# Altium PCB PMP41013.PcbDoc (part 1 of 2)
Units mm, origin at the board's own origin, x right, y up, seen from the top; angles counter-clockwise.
Board outline 51.82 x 50.04 mm, 2 copper layers (Top Layer, Bottom Layer), stack 0.325 mm thick; 134 components, 74 nets, 429 pads, 1513 vias.
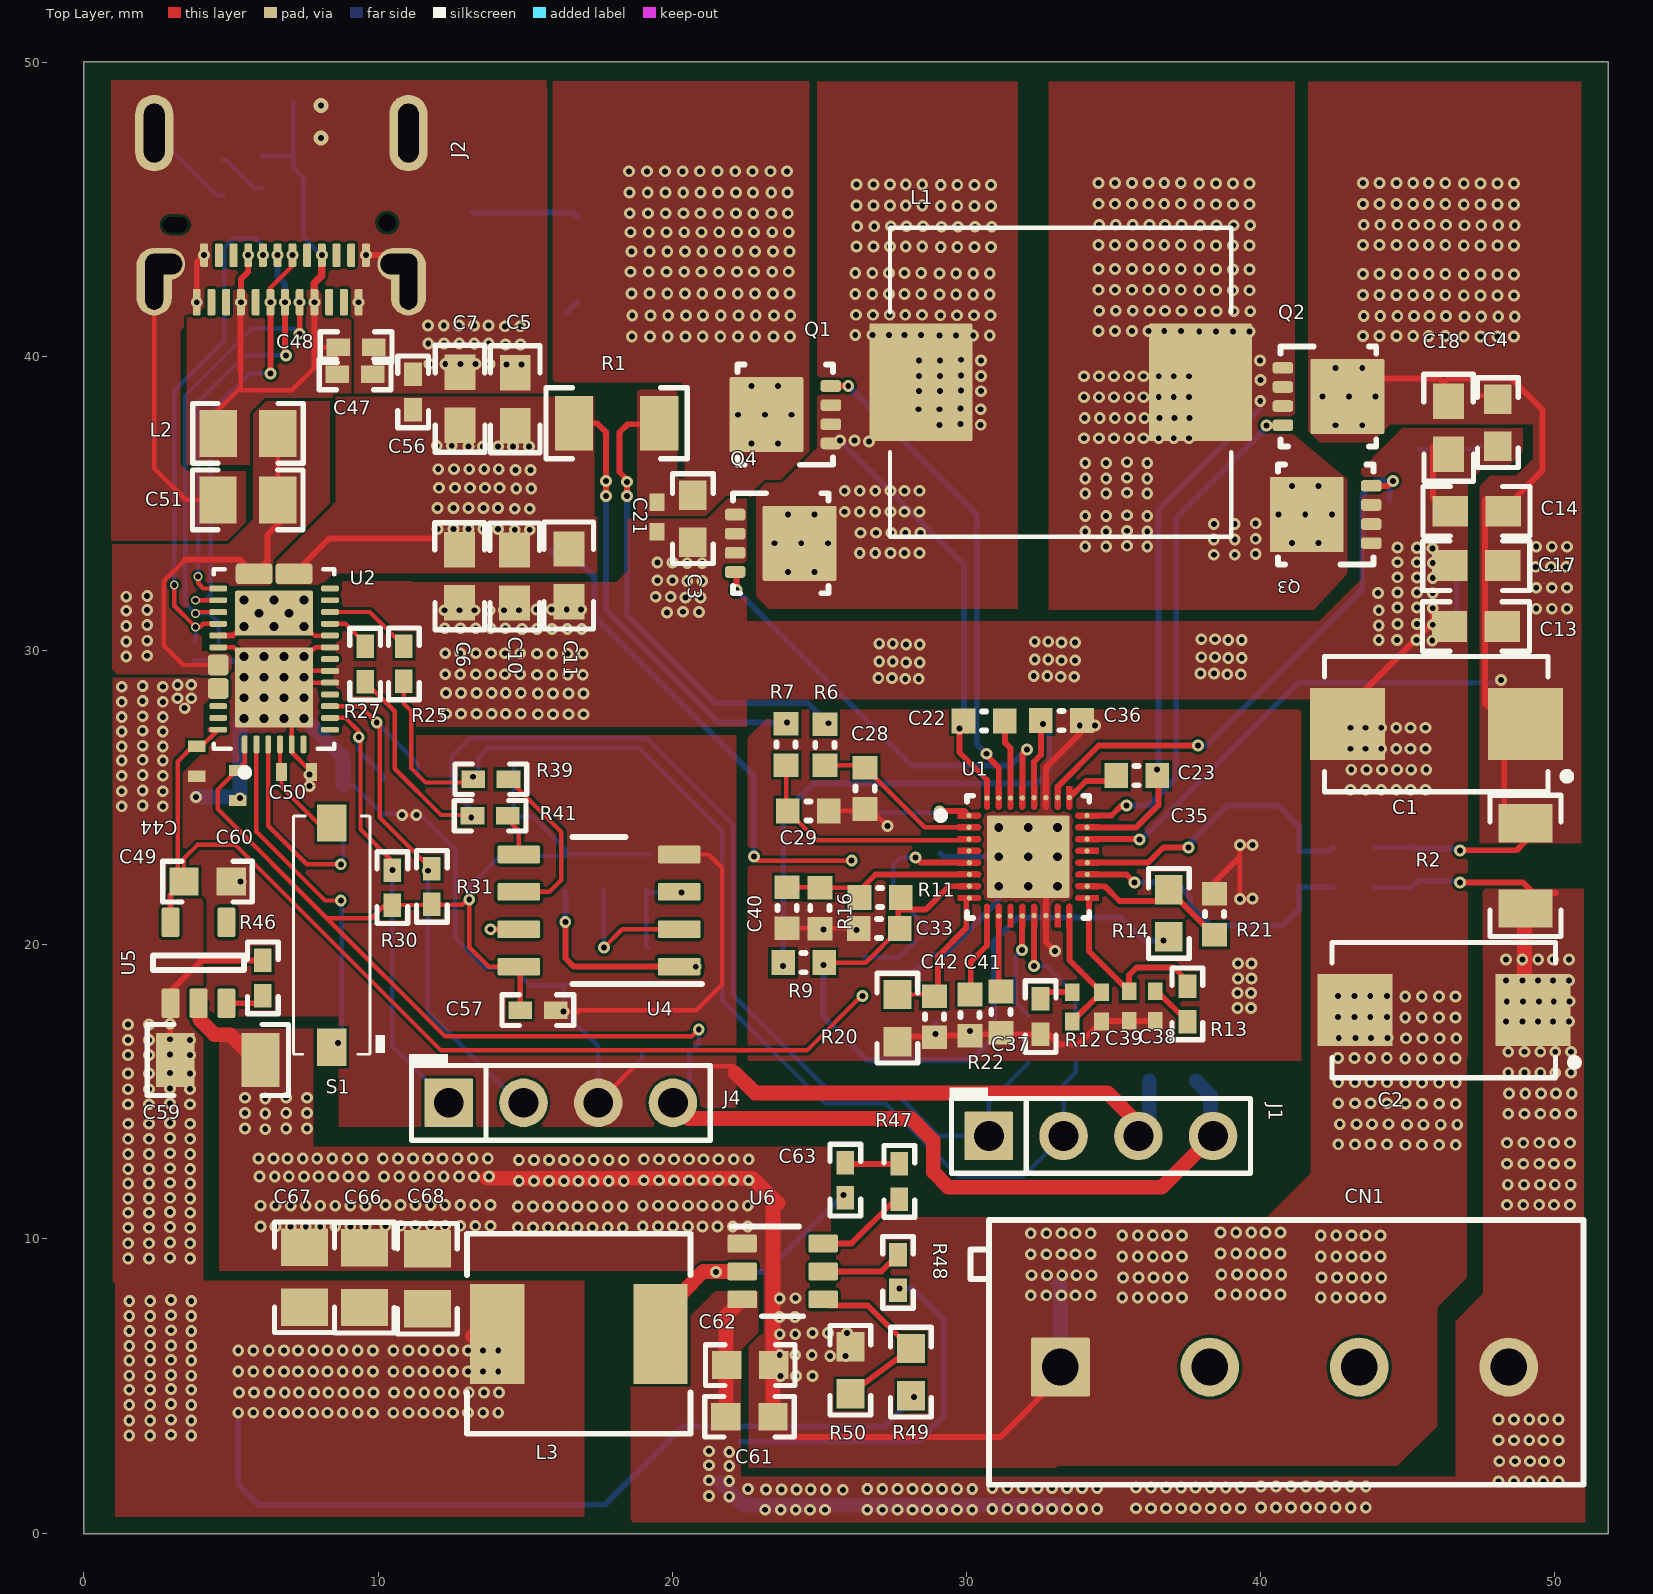
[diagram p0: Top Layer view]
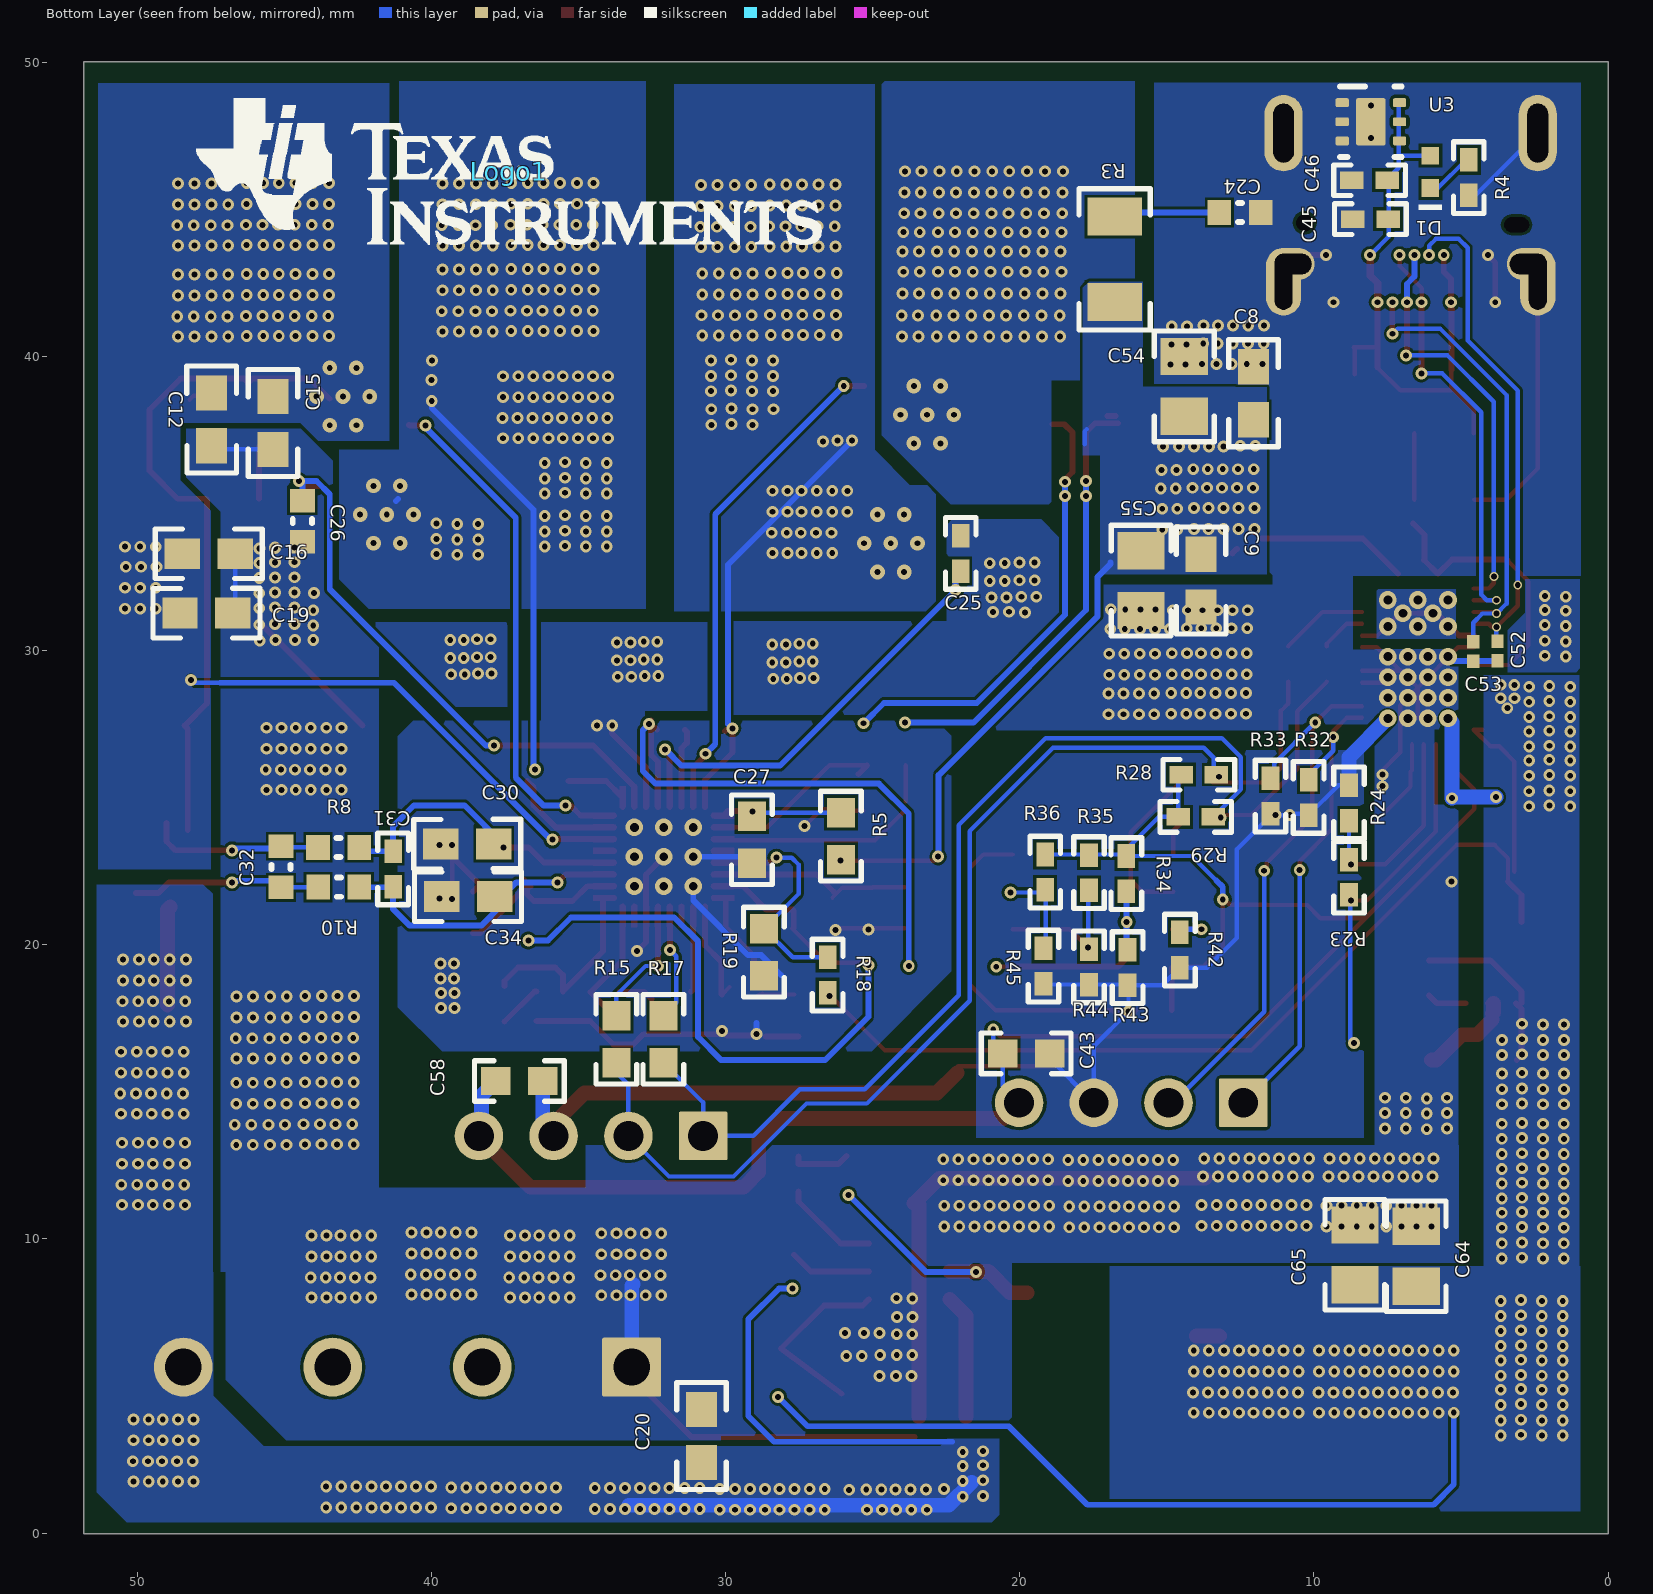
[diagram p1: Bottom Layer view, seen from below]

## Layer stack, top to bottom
Top Solder: solder mask 0.0102, Solder Resist, Dk 3.5
Top Layer: signal copper 0.0356
Dielectric 1: core 0.254, FR-4, Dk 4.2
Bottom Layer: signal copper 0.0356
Bottom Solder: solder mask 0.0102, Solder Resist, Dk 3.5

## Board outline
51.816,50.013 51.816,-0.025 0,-0.025 0,50.013

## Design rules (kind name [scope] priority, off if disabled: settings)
Clearance Clearance_1 [All] p1: gap=0.1 ignorepadtopadclearanceinfootprint=FALSE
ComponentClearance [All] p1: gap=0.05 collisioncheckmode=3 verticalgap=0.05 showdistances=FALSE
DiffPairsRouting [All] p1: maxlimit=0.254 minlimit=0.2 mostfreqgap=0.2 toplayer_minwidth=0.15 toplayer_maxwidth=0.381 toplayer_prefwidth=0.2 bottomlayer_minwidth=0.15 bottomlayer_maxwidth=0.381 bottomlayer_prefwidth=0.2 maxuncoupledlength=12.7
HoleSize [All] p1: absolutevalues=TRUE maxlimit=2.54 minlimit=0.1 maxpercent=80.000 minpercent=20.000
HoleToHoleClearance [All] p1: gap=0.1 allowstackedmicrovias=TRUE
MinimumSolderMaskSliver [All] p1: minsoldermaskwidth=0
NetAntennae [All] p1: netantennaetolerance=0.2
PlaneConnect [All] p1: planeconnectstyle=Direct reliefexpansion=0.508 reliefentries=4 reliefconductorwidth=0.254 reliefairgap=0.254
PolygonConnect [All] p1: connectstyle=Direct reliefconductorwidth=0.254 reliefentries=4 polygonreliefangle="90 Angle" airgapwidth=0.254
RoutingVias [All] p1: holewidth=0.3 width=0.5 viastyle="Through Hole" minholewidth=0.1 minwidth=0.2 maxholewidth=1 maxwidth=1.3
SMDToCorner [All] p1: distance=78740
SilkToSilkClearance [All] p1: silktosilkclearance=0
SilkToSolderMaskClearance [IsPad] p1: minsilkscreentomaskgap=0 clearancetoexposedcopper=TRUE
SolderMaskExpansion [All] p1: expansion=0.102
UnConnectedPin [All] p1:
UnRoutedNet [All] p1: checkbadconnections=TRUE
Width [All] p1: maxlimit=2 minlimit=0.15 preferedwidth=0.2
20 further rules are at their usual default settings.

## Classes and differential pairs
component class PMP41013_Hardware: !PCB Logo1
component class Logo: Logo1
component class Header: J1 J4
component class "TPS25750 USB PD Control": C44 C45 C46 C47 C48 C49 C50 C51 C52 C53 C54 C55 C56 C57 C58 C59 C60 C61 C62 C63 C64 C65 C66 C67 C68 D1 J2 J4 L2 L3 R4 R23 R24 R25 R27 R28 R29 R30 R31 R32 R33 R34 R35 R36 R39 R41 R42 R43 R44 R45 R46 R47 R48 R49 R50 S1 U2 U3 U4 U5 U6
component class "BQ25731 Charger": C1 C2 C3 C4 C5 C6 C7 C8 C9 C10 C11 C12 C13 C14 C15 C16 C17 C18 C19 C20 C21 C22 C23 C24 C25 C26 C27 C28 C29 C30 C31 C32 C33 C34 C35 C36 C37 C38 C39 C40 C41 C42 C43 CN1 J1 L1 Q1 Q2 Q3 Q4 R1 R2 R3 R5 R6 R7 R8 R9 R10 R11 R12 R13 R14 R15 R16 R17 R18 R19 R20 R21 R22 U1
differential pair CSO: +CSO_P -CSO_N

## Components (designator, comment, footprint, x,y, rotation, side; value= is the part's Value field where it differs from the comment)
C1 "Capacitor" 7343-31 45.972,27.5 r180 top value=33uF
C2 "Capacitor" 7343-31 46.229,17.777 r180 top value=33uF
C3 "T521D336M035ATE065" 0603 20.699,34.486 r270 top value=0.01uF
C4 "T521D336M035ATE065" 0603 48.062,37.75 r270 top value=0.01uF
C5 "Capacitor" 0603M 14.666,38.544 r90 top value=10uF
C6 "Capacitor" 0603M 12.775,32.525 r270 top value=10uF
C7 "Capacitor" 0603M 12.79,38.557 r90 top value=10uF
C8 "Capacitor" 0603M 12.057,38.743 r90 bottom value=10uF
C9 "Capacitor" 0603M 13.838,32.378 r270 bottom value=10uF
C10 "Capacitor" 0603M 14.645,32.52 r270 top value=10uF
C11 "Capacitor" 0603M 16.486,32.555 r270 top value=10uF
C12 "Capacitor" 0603M 47.471,37.857 r270 bottom value=10uF
C13 "Capacitor" 0603M 47.319,30.818 r180 top value=10uF
C14 "Capacitor" 0603M 47.344,34.734 r180 top value=10uF
C15 "Capacitor" 0603M 45.386,37.736 r270 bottom value=10uF
C16 "Capacitor" 0603M 47.573,33.291 r180 bottom value=10uF
C17 "Capacitor" 0603M 47.331,32.885 r180 top value=10uF
C18 "Capacitor" 0603M 46.392,37.571 r270 top value=10uF
C19 "Capacitor" 0603M 47.649,31.271 r180 bottom value=10uF
C20 "Capacitor" 0603M 30.82,3.302 r90 bottom value=10uF
C21 "Capacitor" 0402L 19.48,34.544 r270 top value=1000pF
C22 "Capacitor" 0603L 30.603,27.606 r180 top value=0.047uF
C23 "Capacitor" 0603L 35.788,25.745 r0 top value=0.047uF
C24 "Capacitor" 0603L 12.515,44.891 r180 bottom value=1uF
C25 "885012005062" 0402 22.01,33.302 r270 bottom value=150pF
C26 "Capacitor" 0603L 44.388,34.4 r90 bottom value=150pF
C27 "C1608X5R1H474K080AB" 0603 29.107,23.57 r270 bottom value=0.47uF
C28 "Capacitor" 0603L 26.56,25.315 r90 top value=0.033uF
C29 "Capacitor" 0603L 24.627,24.549 r0 top value=0.033uF
C30 "GRM188R71H183KA01D" 0603M 38.785,23.421 r0 bottom value=0.018uF
C31 "GRM155R61A683KA01D" 0402 41.302,22.579 r270 bottom value=0.068uF
C32 "Capacitor" 0603L 45.112,22.648 r270 bottom value=0.1uF
C33 "Capacitor" 0603L 27.036,20.549 r180 top value=1uF
C34 "GRM188R71H183KA01D" 0603M 38.752,21.634 r0 bottom value=0.018uF
C35 "Capacitor" 0402L 34.593,17.889 r90 top value=33pF
C36 "Capacitor" 0603L 33.23,27.616 r0 top value=2.2uF
C37 "885012205029" 0402 32.522,17.559 r270 top value=4700pF
C38 "Capacitor" 0402L 36.422,17.914 r270 top value=680pF
C39 "Capacitor" 0402L 35.533,17.914 r270 top value=15pF
C40 "Capacitor" 0603L 23.911,21.257 r270 top value=100pF
C41 "Capacitor" 0603L 30.123,17.609 r270 top value=100pF
C42 "Capacitor" 0603L 28.912,17.552 r270 top value=100pF
C43 "0603YC104JAT2A" 0603 19.786,16.307 r0 bottom value=0.1uF
C44 "CL05A106MP5NUNC" 0402_070 3.839,26.237 r270 top value=10uF
C45 "C0402C103J5RACTU" 0402 8.082,44.665 r0 bottom value=0.01uF
C46 "C0402C103J5RACTU" 0402 8.112,45.988 r0 bottom value=0.01uF
C47 "C0402C103J5RACTU" 0402 9.22,39.388 r0 top value=0.01uF
C48 "C0402C103J5RACTU" 0402 9.253,40.313 r0 top value=0.01uF
C49 "CL05A106MP5NUNC" 0402_070 5.232,25.413 r90 top value=10uF
C50 "CL05A106MP5NUNC" 0402_070 7.227,25.875 r180 top value=10uF
C51 "C2012X7R1V475M125AC" 0805_HV 5.575,35.122 r180 top value=4.7uF
C52 "CGA1A2X7R1H221K030BA" 0201_033 3.762,29.981 r270 bottom value=220pF
C53 "CGA1A2X7R1H221K030BA" 0201_033 4.588,29.971 r270 bottom value=220pF
C54 "C2012X5R1V226M125AC" 0805_HV 14.41,38.981 r90 bottom value=22uF
C55 "C2012X5R1V226M125AC" 0805_HV 15.873,32.378 r270 bottom value=22uF
C56 "GMK105BJ104KV-F" 0402 11.192,38.791 r90 top value=0.1uF
C57 "GMK105BJ104KV-F" 0402 15.435,17.776 r0 top value=0.1uF
C58 "0603YC104JAT2A" 0603 37.012,15.37 r0 bottom value=0.1uF
C59 "GRM31MR71H105KA88L" 1206 4.557,16.081 r0 top value=1uF
C60 "CGA3E3X5R1A225K080AB" 0603 4.205,22.144 r0 top value=2.2uF
C61 "C3225X5R1H106K250AB" 0603 22.627,3.956 r0 top value=10uF
C62 "C1608X5R1H224K080AB" 0603 22.652,5.709 r0 top value=0.22uF
C63 "GRM155R61H104ME14D" 0402 25.887,11.996 r270 top value=0.1uF
C64 "GRM219R61C226ME15L" 0805_HV 6.525,9.409 r90 bottom value=22uF
C65 "GRM219R61C226ME15L" 0805_HV 8.608,9.46 r90 bottom value=22uF
C66 "GRM219R61C226ME15L" 0805_HV 9.534,8.684 r90 top value=22uF
C67 "GRM219R61C226ME15L" 0805_HV 7.502,8.698 r90 top value=22uF
C68 "GRM219R61C226ME15L" 0805_HV 11.678,8.647 r90 top value=22uF
CN1 "ED120/4DS" On-Shore_ED120_4DS 40.814,5.643 r0 top
D1 "LW QH8G-Q2S2-3K5L-1" "LW QH8G_White" 6.046,46.271 r270 bottom value=White
J1 "TSW-104-07-G-S" TSW-104-07-G-S 34.575,13.502 r0 top
J2 "DX07S024JJ2R1300" JAE_DX07S024JJ2R1300 6.714,49.39 r180 top
J4 "TSW-104-07-G-S" TSW-104-07-G-S 16.215,14.629 r0 top
L1 "BMQADY1010404R7MA1" FP-BMQADY1010404R7MA1_SMD2-MFG 33.203,39.119 r0 top
L2 "FBMJ2125HM210NT" 0805_HV 5.581,37.38 r0 top value="21 ohm"
L3 "SRP6540-5R6M" SRP6540 16.827,6.777 r180 top value=5.6uH
Logo1 "Texas Instruments" TI_Stacked_Overlay_Small 37.363,46.279 r180 bottom
Q1 "CSD17577Q3A" DNH0008A 23.846,38.017 r180 top value=30V
Q2 "CSD17577Q3A" DNH0008A 42.307,38.636 r0 top value=30V
Q3 "CSD17577Q3A" DNH0008A 42.214,34.625 r180 top value=30V
Q4 "CSD17577Q3A" DNH0008A 23.688,33.647 r0 top value=30V
R1 "Resistor" 1206 18.111,37.727 r0 top value=0.01
R2 "Resistor" 1206 49.006,22.683 r270 top value=0.01
R3 "CRCW12063R90JNEA" 1206 16.776,43.301 r270 bottom value=3.9
R4 "CRCW040210K0JNED" 0402 4.738,46.076 r90 bottom value=10k
R5 "RC0603FR-071RL" 0603 26.079,23.693 r90 bottom value=1.00
R6 "Resistor" 0603L 25.187,26.796 r90 top value=4.99
R7 "Resistor" 0603L 23.872,26.806 r90 top value=4.99
R8 "Resistor" 0603L 43.156,23.309 r180 bottom value=10
R9 "Resistor" 0603L 24.47,19.39 r0 top value=10.0
R10 "Resistor" 0603L 43.148,21.956 r180 bottom value=10
R11 "Resistor" 0603L 27.067,21.604 r180 top value=383k
R12 "Resistor" 0402L 33.603,17.889 r270 top value=40.2k
R13 "CRCW040215K0FKED" 0402 37.514,17.99 r270 top value=15.0k
R14 "CRCW06031K00FKEA" 0603 36.879,21.067 r270 top value=1.00k
R15 "RMCF0603ZT0R00" 0603 33.712,16.788 r90 bottom value=0
R16 "RC0603FR-07220KL" 0603L 25.018,21.243 r270 top value=220k
R17 "RMCF0603ZT0R00" 0603 32.112,16.788 r90 bottom value=0
R18 "CRCW04021K00FKED" 0402 26.531,18.971 r90 bottom value=1.00k
R19 "CRCW060310K0FKEA" 0603 28.699,19.749 r90 bottom value=10.0k
R20 "CRCW0603191KFKEA" 0603 27.657,17.508 r90 top value=191k
R21 "RC0603FR-07120KL" 0603L 38.432,21.04 r270 top value=120k
R22 "Resistor" 0603L 31.171,17.711 r270 top value=30.1k
R23 "RC0402JR-070RL" 0402 8.81,22.294 r270 bottom value=0
R24 "RMCF0402FT100K" 0402 8.812,24.823 r270 bottom value=100k
R25 "RC0402JR-070RL" 0402 10.881,29.549 r270 top value=0
R27 "RC0402JR-070RL" 0402 9.561,29.543 r270 top value=0
R28 "CRCW04022K20FKED" 0402 13.915,25.781 r180 bottom value=2.20k
R29 "CRCW04022K20FKED" 0402 14.019,24.349 r180 bottom value=2.20k
R30 "CRCW04022K20FKED" 0402 10.488,21.939 r270 top value=2.20k
R31 "CRCW04022K20FKED" 0402 11.831,21.985 r270 top value=2.20k
R32 "RC0402JR-070RL" 0402 10.183,25.009 r90 bottom value=0
R33 "RC0402JR-070RL" 0402 11.48,25.052 r90 bottom value=0
R34 "CRCW040210K0JNED" 0402 16.378,22.416 r90 bottom value=10k
R35 "CRCW040210K0JNED" 0402 17.647,22.449 r90 bottom value=10k
R36 "CRCW040210K0JNED" 0402 19.137,22.468 r90 bottom value=10k
R39 "RC0402JR-070RL" 0402 13.836,25.626 r0 top value=0
R41 "RC0402JR-070RL" 0402 13.813,24.383 r0 top value=0
R42 "CRCW040210K0JNED" 0402 14.56,19.818 r90 bottom value=10k
R43 "CRCW040210K0JNED" 0402 16.338,19.222 r90 bottom value=10k
R44 "CRCW040210K0JNED" 0402 17.647,19.248 r90 bottom value=10k
R45 "CRCW040210K0JNED" 0402 19.193,19.274 r90 bottom value=10k
R46 "RC0402JR-070RL" 0402 6.086,18.871 r90 top value=0
R47 "CRCW040230R0JNED" 0402 27.723,11.954 r90 top value=30
R48 "RC0402JR-070RL" 0402 27.677,8.864 r270 top value=0
R49 "CRCW060352K3FKEA" 0603 28.115,5.475 r270 top value=52.3k
R50 "CRCW060310K0FKEA" 0603 26.056,5.538 r270 top value=10.0k
S1 "CHS-01TB" SW_CHS-01TB 8.427,20.327 r180 top
U1 "BQ25731RSN" RSN0032B-MFG 32.101,22.99 r0 top
U2 "TPS25750DRJK" RJK0038B-C01-MFG 6.468,29.709 r90 top
U3 "TVS2200DRVR" DRV0006A 8.065,47.974 r180 bottom
U4 "CAT24C256WI-G" SOIC-8 17.512,21.162 r180 top
U5 "TPS76333DBVR" DBV0005A_N 3.899,19.388 r90 top
U6 "TPS56339DDCR" DDC0006A_N 23.756,8.895 r0 top

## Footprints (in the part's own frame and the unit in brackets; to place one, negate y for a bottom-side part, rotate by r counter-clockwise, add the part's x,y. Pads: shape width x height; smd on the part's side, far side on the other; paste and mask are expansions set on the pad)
0201_033 [mm] "SMD, 2-Leads, Height 0.33mm"
  rect 0.46x0.42 smd mask+0.048: 1(-0.33,0) 2(0.33,0)
  body extent -0.31,-0.16 0.31,0.16, height 0.33
0402 [mm] "0402 from SM-752 data"
  rect 0.8x0.6 smd: 1(-0.6,0) 2(0.6,0)
  silkscreen extent -1.22,-0.52 1.22,0.52, body extent -0.55,-0.3 0.55,0.3, height 0.6
0402_070 [mil] "SMD, 2-Leads, Body 1.2x0.7mm, Height 0.7mm"
  rect 15x24 smd: 1(-20,0) 2(20,0)
  body extent -24,-14 24,14, height 28
0402L [mm] "0402 from SM-752 data"
  rect 0.6x0.5 smd: 1(-0.5,0) 2(0.5,0)
  body extent -0.55,-0.3 0.55,0.3, height 0.6
0603 [mm] "0603 from SM-752 data"
  rect 1x0.95 smd: 1(-0.8,0) 2(0.8,0)
  silkscreen extent -1.52,-0.69 1.52,0.69, body extent -0.87,-0.47 0.87,0.47, height 1
0603L [mm] "0603 from SM-752 data"
  rect 0.8x0.85 smd: 1(-0.7,0) 2(0.7,0)
  silkscreen extent -0.07,-0.33 0.07,0.33, body extent -0.87,-0.47 0.87,0.47, height 1
0603M [mm] "0603 from SM-752 data"
  rect 1.2x1.05 smd: 1(-0.9,0) 2(0.9,0)
  silkscreen extent -1.82,-0.84 1.82,0.84, body extent -0.87,-0.47 0.87,0.47, height 1
0805_HV [mil] "0805 with 30mil clearance between pads"
  rect 50x63 smd: 1(-40,0) 2(40,0)
  silkscreen extent -74,-40 74,40, body extent -43,-29 43,29, height 57
1206 [mm] "1206 from SM-752 data"
  rect 1.3x1.85 smd: 1(-1.45,0) 2(1.45,0)
  silkscreen extent -2.4,-1.21 2.4,1.21, body extent -1.7,-0.9 1.7,0.9, height 1.35
7343-31 [mm] "Medium Density based on Kemet T495 dimensions"
  rect 2.55x2.45 smd: 1(-3.025,0) 2(3.025,0)
  silkscreen extent -4.56,-2.3 3.8,2.3, body extent -3.8,-2.3 3.8,2.3, height 3.1
DBV0005A_N [mm] "SOT23, 5-Leads, Body 2.9x1.6mm, Pitch 0.95mm, Lead Span 2.8mm, IPC Medium Density"
  rrect17% 1x0.6 smd: 1(-1.375,0.95) 2(-1.375,0) 3(-1.375,-0.95) 4(1.375,-0.95) 5(1.375,0.95)
  silkscreen extent -0.25,-1.55 0.25,1.55, body extent -1.42,-1.46 1.42,1.46, height 1.09
DDC0006A_N [mm]
  rrect17% 1x0.6 smd: 1(-1.375,0.95) 2(-1.375,0) 3(-1.375,-0.95) 4(1.375,-0.95) 5(1.375,0) 6(1.375,0.95)
  silkscreen extent -1.75,-1.52 0.7,1.53, body extent -1.43,-1.48 1.43,1.49, height 0.92
DNH0008A [mm] "VSONP-8"
  rrect50% 0.7x0.4 smd paste-0.05 mask-0.05: 1(-1.55,0.975) 2(-1.55,0.325) 3(-1.55,-0.325) 4(-1.55,-0.975) 5(1.55,-0.975) 6(1.55,-0.325) 7(1.55,0.325) 8(1.55,0.975)
  rrect4% 2.51x2.55 smd paste-1.5 mask-1.5: 9(0.645,0)
  rrect14% 0.705x1.125 on Top Paste: 9A(-0.208,0.662) 9B(0.697,0.662) 9C(-0.208,-0.663) 9D(0.697,-0.663)
  silkscreen extent -1.62,-1.7 1.62,1.7, body extent -1.65,-1.65 1.65,1.66, height 0.91
DRV0006A [mm] "SON, 6-Leads, Body 2x2mm, Pitch 0.65mm, Thermal Pad 1.6x1mm, TI Recommended"
  rrect33% 0.45x0.3 smd: 1(-0.975,0.65) 2(-0.975,0) 3(-0.975,-0.65) 4(0.975,-0.65) 5(0.975,0) 6(0.975,0.65)
  rrect14% 1x0.7 on Bottom Paste: 7(0,-0.45) 7(0,0.45)
  rrect10% 1x1.6 smd paste-0.5: 7(0,0)
  silkscreen extent -1.05,-1.2 1.05,1.2, body extent -1.05,-1.05 1.05,1.05, height 0.81
FP-BMQADY1010404R7MA1_SMD2-MFG [mm]
  rrect3% 3.5x4 smd paste+0 mask+0: 1(-4.75,0) 2(4.75,0)
  silkscreen extent -5.8,-5.25 5.8,5.25, body extent -6.6,-5.35 6.6,5.35, height 0.25
JAE_DX07S024JJ2R1300 [mm] "Receptacle, USB 3.1 Type C, R/A, SMT"
  rrect37% 0.27x0.9 smd: A1(-2.625,7.55) A2(-2.125,7.55) A3(-1.625,7.55) A4(-1.125,7.55) A5(-0.625,7.55) A6(-0.125,7.55) A7(0.375,7.55) A8(0.875,7.55) A9(1.375,7.55) A10(1.875,7.55) A11(2.375,7.55) A12(2.875,7.55)
  round 0.3 hole 0.6 unplated mask+0.102: ALIGN1(-3.6,4.85)
  rrect100% 0.55x0.3 hole 0.5 slot 0.85 at 0 deg unplated mask+0.102: ALIGN2(3.6,4.915)
  rrect37% 0.27x0.8 smd: B1(2.625,5.95) B2(2.125,5.95) B3(1.625,5.95) B4(1.125,5.95) B5(0.625,5.95) B6(0.125,5.95) B7(-0.375,5.95) B8(-0.875,5.95) B9(-1.375,5.95) B10(-1.875,5.95) B11(-2.375,5.95) B12(-2.875,5.95)
  rrect100% 1.2x2.3 hole 0.6 slot 1.9 at 90 deg: S1(-4.32,6.85) S2(4.32,6.85)
  rrect100% 1.45x1.1 hole 0.7 slot 1.25 at 0 deg: S1(-3.995,6.25) S2(3.995,6.25)
  rrect100% 1.3x2.6 hole 0.7 slot 2 at 90 deg: S3(-4.32,1.8) S4(4.32,1.8)
  body extent -4.47,-0.5 4.47,7.67, height 3.14
"LW QH8G_White" [mm] "SMD, 2-Leads, Body 1x0.5mm"
  rect 0.6x0.6 smd paste-0.3: 1(-0.55,0) 2(0.55,0)
  silkscreen extent 1.1,-0.4 1.3,0.4, body extent -0.55,-0.3 0.55,0.3, height 0.4
On-Shore_ED120_4DS [mm] "ONSHORE"
  rrect5% 2x2 hole 1.25: 1(-7.62,0)
  round 2 hole 1.25: 2(-2.54,0) 3(2.54,0) 4(7.62,0)
  silkscreen extent -10.68,-4 10.16,5, body extent -10.86,-4 10.16,5, height 13
RJK0038B-C01-MFG [mm]
  rrect50% 0.6x0.2 smd paste+0 mask-1000: 1(-2.9,1) 2(-2.9,0.6) 3(-2.9,0.2) 4(-2.9,-0.2) 5(-2.9,-0.6) 6(-2.9,-1)
  rrect50% 0.2x0.6 smd paste+0 mask-1000: 7(-2.4,-1.9) 8(-2,-1.9) 9(-1.6,-1.9) 10(-1.2,-1.9) 11(-0.8,-1.9) 12(-0.4,-1.9) 13(0,-1.9) 14(0.4,-1.9) 15(0.8,-1.9) 16(1.2,-1.9) 17(1.6,-1.9) 18(2,-1.9) 19(2.4,-1.9) 26(2.4,1.9) 27(2,1.9) 28(1.6,1.9) 29(1.2,1.9) 30(0.8,1.9) 31(0.4,1.9) 36(-1.6,1.9) 37(-2,1.9) 38(-2.4,1.9)
  rrect29% 0.7x1.253 smd paste-1000 mask-1000: 20-21-22(2.9,-0.677) 23-24-25(2.9,0.677)
  rrect29% 0.7x0.7 smd paste-1000 mask-1000: 32-33(-0.2,1.9) 34-35(-1,1.9)
  rrect4% 2.72x2.65 smd paste-1000 mask-1000: 39(-0.965,0)
  rrect7% 1.53x2.65 smd paste-1000 mask-1000: 40(1.56,0)
  silkscreen extent -3.97,-2.05 3.05,2.05, body extent -3.3,-2.3 3.35,2.35, height 0.25
RSN0032B-MFG [mm]
  round 0.18 smd paste+0 mask+0: 1(-2.01,1.4) 2(-2.01,1) 3(-2.01,0.6) 4(-2.01,0.2) 5(-2,-0.2) 6(-2,-0.6) 7(-2,-1) 8(-2,-1.4) 9(-1.4,-2.01) 10(-1,-2.01) 11(-0.6,-2.01) 12(-0.2,-2.01) 13(0.2,-2) 14(0.6,-2) 15(1,-2) 16(1.4,-2) 17(2.01,-1.4) 18(2.01,-1) 19(2.01,-0.6) 20(2.01,-0.2) 21(2,0.2) 22(2,0.6) 23(2,1) 24(2,1.4) 25(1.4,2.01) 26(1,2.01) 27(0.6,2.01) 28(0.2,2.01) 29(-0.2,2) 30(-0.6,2) 31(-1,2) 32(-1.4,2)
  rrect4% 2.8x2.8 smd paste-1000 mask+0: 33(0,0)
  Top Layer region: -1.3,2.4 -1.3,1.7 -1.313,1.65 -1.35,1.613 -1.4,1.6 -1.4,1.6 -1.438,1.608 -1.471,1.629 -1.492,1.662 -1.5,1.7 -1.5,1.7 -1.5,2.4
  Top Layer region: -0.9,2.4 -0.9,1.7 -0.908,1.662 -0.929,1.629 -0.962,1.608 -1,1.6 -1,1.6 -1.038,1.608 -1.071,1.629 -1.092,1.662 -1.1,1.7 -1.1,1.7 -1.1,2.4
  Top Layer region: -0.5,2.4 -0.5,1.7 -0.508,1.662 -0.529,1.629 -0.562,1.608 -0.6,1.6 -0.6,1.6 -0.638,1.608 -0.671,1.629 -0.692,1.662 -0.7,1.7 -0.7,1.7 -0.7,2.4
  Top Layer region: -0.1,2.4 -0.1,1.7 -0.108,1.662 -0.129,1.629 -0.162,1.608 -0.2,1.6 -0.2,1.6 -0.238,1.608 -0.271,1.629 -0.292,1.662 -0.3,1.7 -0.3,1.7 -0.3,2.4
  Top Layer region: 0.3,2.4 0.3,1.7 0.292,1.662 0.271,1.629 0.238,1.608 0.2,1.6 0.2,1.6 0.162,1.608 0.129,1.629 0.108,1.662 0.1,1.7 0.1,1.7 0.1,2.4
  Top Layer region: 0.7,2.4 0.7,1.7 0.687,1.65 0.65,1.613 0.6,1.6 0.6,1.6 0.562,1.608 0.529,1.629 0.508,1.662 0.5,1.7 0.5,1.7 0.5,2.4
  Top Layer region: 1.1,2.4 1.1,1.7 1.092,1.662 1.071,1.629 1.038,1.608 1,1.6 1,1.6 0.962,1.608 0.929,1.629 0.908,1.662 0.9,1.7 0.9,1.7 0.9,2.4
  Top Layer region: 1.5,2.4 1.5,1.7 1.492,1.662 1.471,1.629 1.438,1.608 1.4,1.6 1.4,1.6 1.362,1.608 1.329,1.629 1.308,1.662 1.3,1.7 1.3,1.7 1.3,2.4
  Top Layer region: 2.4,1.3 1.7,1.3 1.662,1.308 1.629,1.329 1.608,1.362 1.6,1.4 1.6,1.4 1.608,1.438 1.629,1.471 1.662,1.492 1.7,1.5 1.7,1.5 2.4,1.5
  Top Layer region: 2.4,0.9 1.7,0.9 1.662,0.908 1.629,0.929 1.608,0.962 1.6,1 1.6,1 1.608,1.038 1.629,1.071 1.662,1.092 1.7,1.1 1.7,1.1 2.4,1.1
  Top Layer region: 2.4,0.5 1.7,0.5 1.662,0.508 1.629,0.529 1.608,0.562 1.6,0.6 1.6,0.6 1.608,0.638 1.629,0.671 1.662,0.692 1.7,0.7 1.7,0.7 2.4,0.7
  Top Layer region: 2.4,0.1 1.7,0.1 1.662,0.108 1.629,0.129 1.608,0.162 1.6,0.2 1.6,0.2 1.608,0.238 1.629,0.271 1.662,0.292 1.7,0.3 1.7,0.3 2.4,0.3
  Top Layer region: 2.4,-0.3 1.7,-0.3 1.662,-0.292 1.629,-0.271 1.608,-0.238 1.6,-0.2 1.6,-0.2 1.608,-0.162 1.629,-0.129 1.662,-0.108 1.7,-0.1 1.7,-0.1 2.4,-0.1
  Top Layer region: 2.4,-0.7 1.7,-0.7 1.662,-0.692 1.629,-0.671 1.608,-0.638 1.6,-0.6 1.6,-0.6 1.608,-0.562 1.629,-0.529 1.662,-0.508 1.7,-0.5 1.7,-0.5 2.4,-0.5
  Top Layer region: 2.4,-1.1 1.7,-1.1 1.662,-1.092 1.629,-1.071 1.608,-1.038 1.6,-1 1.6,-1 1.608,-0.962 1.629,-0.929 1.662,-0.908 1.7,-0.9 1.7,-0.9 2.4,-0.9
  Top Layer region: 2.4,-1.5 1.7,-1.5 1.662,-1.492 1.629,-1.471 1.608,-1.438 1.6,-1.4 1.6,-1.4 1.608,-1.362 1.629,-1.329 1.662,-1.308 1.7,-1.3 1.7,-1.3 2.4,-1.3
  Top Layer region: 1.3,-2.4 1.3,-1.7 1.308,-1.662 1.329,-1.629 1.362,-1.608 1.4,-1.6 1.4,-1.6 1.438,-1.608 1.471,-1.629 1.492,-1.662 1.5,-1.7 1.5,-1.7 1.5,-2.4
  Top Layer region: 0.9,-2.4 0.9,-1.7 0.908,-1.662 0.929,-1.629 0.962,-1.608 1,-1.6 1,-1.6 1.038,-1.608 1.071,-1.629 1.092,-1.662 1.1,-1.7 1.1,-1.7 1.1,-2.4
  Top Layer region: 0.5,-2.4 0.5,-1.7 0.508,-1.662 0.529,-1.629 0.562,-1.608 0.6,-1.6 0.6,-1.6 0.638,-1.608 0.671,-1.629 0.692,-1.662 0.7,-1.7 0.7,-1.7 0.7,-2.4
  Top Layer region: 0.1,-2.4 0.1,-1.7 0.108,-1.662 0.129,-1.629 0.162,-1.608 0.2,-1.6 0.2,-1.6 0.238,-1.608 0.271,-1.629 0.292,-1.662 0.3,-1.7 0.3,-1.7 0.3,-2.4
  Top Layer region: -0.3,-2.4 -0.3,-1.7 -0.292,-1.662 -0.271,-1.629 -0.238,-1.608 -0.2,-1.6 -0.2,-1.6 -0.162,-1.608 -0.129,-1.629 -0.108,-1.662 -0.1,-1.7 -0.1,-1.7 -0.1,-2.4
  Top Layer region: -0.7,-2.4 -0.7,-1.7 -0.692,-1.662 -0.671,-1.629 -0.638,-1.608 -0.6,-1.6 -0.6,-1.6 -0.562,-1.608 -0.529,-1.629 -0.508,-1.662 -0.5,-1.7 -0.5,-1.7 -0.5,-2.4
  Top Layer region: -1.1,-2.4 -1.1,-1.7 -1.092,-1.662 -1.071,-1.629 -1.038,-1.608 -1,-1.6 -1,-1.6 -0.962,-1.608 -0.929,-1.629 -0.908,-1.662 -0.9,-1.7 -0.9,-1.7 -0.9,-2.4
  Top Layer region: -1.5,-2.4 -1.5,-1.7 -1.492,-1.662 -1.471,-1.629 -1.438,-1.608 -1.4,-1.6 -1.4,-1.6 -1.362,-1.608 -1.329,-1.629 -1.308,-1.662 -1.3,-1.7 -1.3,-1.7 -1.3,-2.4
  Top Layer region: -2.4,-1.3 -1.7,-1.3 -1.662,-1.308 -1.629,-1.329 -1.608,-1.362 -1.6,-1.4 -1.6,-1.4 -1.613,-1.45 -1.65,-1.487 -1.7,-1.5 -1.7,-1.5 -2.4,-1.5
  Top Layer region: -2.4,-0.9 -1.7,-0.9 -1.662,-0.908 -1.629,-0.929 -1.608,-0.962 -1.6,-1 -1.6,-1 -1.608,-1.038 -1.629,-1.071 -1.662,-1.092 -1.7,-1.1 -1.7,-1.1 -2.4,-1.1
  Top Layer region: -2.4,-0.5 -1.7,-0.5 -1.662,-0.508 -1.629,-0.529 -1.608,-0.562 -1.6,-0.6 -1.6,-0.6 -1.608,-0.638 -1.629,-0.671 -1.662,-0.692 -1.7,-0.7 -1.7,-0.7 -2.4,-0.7
  Top Layer region: -2.4,-0.1 -1.7,-0.1 -1.662,-0.108 -1.629,-0.129 -1.608,-0.162 -1.6,-0.2 -1.6,-0.2 -1.608,-0.238 -1.629,-0.271 -1.662,-0.292 -1.7,-0.3 -1.7,-0.3 -2.4,-0.3
  Top Layer region: -2.4,0.3 -1.7,0.3 -1.662,0.292 -1.629,0.271 -1.608,0.238 -1.6,0.2 -1.6,0.2 -1.608,0.162 -1.629,0.129 -1.662,0.108 -1.7,0.1 -1.7,0.1 -2.4,0.1
  Top Layer region: -2.4,0.7 -1.7,0.7 -1.662,0.692 -1.629,0.671 -1.608,0.638 -1.6,0.6 -1.6,0.6 -1.608,0.562 -1.629,0.529 -1.662,0.508 -1.7,0.5 -1.7,0.5 -2.4,0.5
  Top Layer region: -2.4,1.1 -1.7,1.1 -1.662,1.092 -1.629,1.071 -1.608,1.038 -1.6,1 -1.6,1 -1.608,0.962 -1.629,0.929 -1.662,0.908 -1.7,0.9 -1.7,0.9 -2.4,0.9
  Top Layer region: -2.4,1.5 -1.7,1.5 -1.662,1.492 -1.629,1.471 -1.608,1.438 -1.6,1.4 -1.6,1.4 -1.608,1.362 -1.629,1.329 -1.662,1.308 -1.7,1.3 -1.7,1.3 -2.4,1.3
  silkscreen extent -3.1,-2.07 2.07,2.07, body extent -2.5,-2.5 2.5,2.5, height 0.25
SOIC-8 [mm] "duplicate of SO-8.  SOIC, 8-Leads, Body 5.0x4.0mm (max), Pitch 1.27mm, IPC Medium Density"
  rrect17% 1.45x0.6 smd: 1(-2.725,1.905) 2(-2.725,0.635) 3(-2.725,-0.635) 4(-2.725,-1.905) 5(2.725,-1.905) 6(2.725,-0.635) 7(2.725,0.635) 8(2.725,1.905)
  silkscreen extent -3.5,-2.5 0.9,2.5, body extent -3,-2.45 3,2.45, height 1.63
SRP6540 [mm] "Bourns"
  rect 1.85x3.4 smd: 1(-2.775,0) 2(2.775,0)
  silkscreen extent -3.8,-3.4 3.8,3.4, body extent -3.75,-3.35 3.75,3.35, height 4
SW_CHS-01TB [mm] "CHS Recommended footprint"
  rect 1x1.27 smd: 1(0,3.81) 2(0,-3.81)
  silkscreen extent -1.8,-4.05 1.3,4.05, body extent -1.25,-4 1.25,4, height 2.51
TI_Stacked_Overlay_Small [mm]
  silkscreen extent -10.63,-2.49 10.63,2.49
TSW-104-07-G-S [mm] "Samtec 100mil, 1x4, 230 mil above insulator"
  rrect6% 1.65x1.65 hole 1.016: 1(-3.81,0)
  round 1.65 hole 1.016: 2(-1.27,0) 3(1.27,0) 4(3.81,0)
  silkscreen extent -5.16,-1.27 5.08,1.65, body extent -5.08,-1.27 5.08,1.27, height 8.38

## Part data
C1 C2: library part CMP-0011849-2, "CAP, TA, 33 uF, 35 V, +/- 20%, 0.065 ohm, SMD", Cap_Case=7343-31, Manufacturer=Kemet, PartNumber=T521D336M035ATE065, Supplier Part Number 1=399-9786-1-ND, Tolerance_%=20%, Value1="0.065 ohm", Value2=35V, ValueDisplayed=33uF
C3 C4: library part CMP-0007403-4, "CAP, CERM, 0.01 uF, 25 V, +/- 10%, X7R, 0603", Cap_Case=0603, Manufacturer=MuRata, PartNumber=GRM188R71E103KA01D, Supplier Part Number 1=490-1520-1-ND, TempCo=X7R, Tolerance_%=10%, Value1=Unknown, Value2=25V, ValueDisplayed=0.01uF
C5 C6 C7 C8 C9 C10 C11 C12 C13 C14 C15 C16 C17 C18 C19 C20 C61: library part CMP-0007344-5, "CAP, CERM, 10 uF, 25 V, +/- 20%, X5R, 0603", Cap_Case=0603, Manufacturer=MuRata, PartNumber=GRM188R61E106MA73D, Supplier Part Number 1=490-7202-1-ND, TempCo=X5R, Tolerance_%=20%, Value1=Unknown, Value2=25V, ValueDisplayed=10uF
C21: library part CMP-0006234-2, "CAP, CERM, 1000 pF, 25 V, +/- 5%, X7R, 0402", Cap_Case=0402, Manufacturer=Kemet, PartNumber=C0402C102J3RACTU, Supplier Part Number 1=399-7752-1-ND, TempCo=X7R, Tolerance_%=5%, Value1=Unknown, Value2=25V, ValueDisplayed=1000pF
C22 C23: library part CMP-0007423-4, "CAP, CERM, 0.047 uF, 25 V, +/- 10%, X7R, 0603", Cap_Case=0603, Manufacturer=MuRata, PartNumber=GRM188R71E473KA01D, Supplier Part Number 1=490-1522-1-ND, TempCo=X7R, Tolerance_%=10%, Value1=Unknown, Value2=25V, ValueDisplayed=0.047uF
C24 C33: library part CMP-0007405-4, "CAP, CERM, 1 uF, 25 V, +/- 10%, X7R, 0603", Cap_Case=0603, Manufacturer=MuRata, PartNumber=GRM188R71E105KA12D, Supplier Part Number 1=490-5307-1-ND, TempCo=X7R, Tolerance_%=10%, Value1=Unknown, Value2=25V, ValueDisplayed=1uF
C25: library part CMP-0064913-2, "CAP, CERM, 150 pF, 50 V,+/- 5%, C0G/NP0, 0402", Cap_Case=0402, Manufacturer="Wurth Elektronik", Supplier Part Number 1=732-7476-1-ND, TempCo=C0G/NP0, Tolerance_%=5%, Value1=Unknown, Value2=50V, ValueDisplayed=150pF
C26: library part CMP-0006880-4, "CAP, CERM, 150 pF, 50 V, +/- 5%, C0G/NP0, 0603", Cap_Case=0603, Manufacturer=Kemet, PartNumber=C0603C151J5GACTU, Supplier Part Number 1=399-1063-1-ND, TempCo=C0G/NP0, Tolerance_%=5%, Value1=Unknown, Value2=50V, ValueDisplayed=150pF
C27: library part CMP-0007016-5, "CAP, CERM, 0.47 uF, 50 V, +/- 10%, X5R, 0603", Cap_Case=0603, Manufacturer=TDK, Supplier Part Number 1=445-7464-1-ND, TempCo=X5R, Tolerance_%=10%, Value1="0.010974 ohm", Value2=50V, ValueDisplayed=0.47uF
C28 C29: library part CMP-0007419-4, "CAP, CERM, 0.033 uF, 25 V, +/- 10%, X7R, 0603", Cap_Case=0603, Manufacturer=MuRata, PartNumber=GRM188R71E333KA01D, Supplier Part Number 1=490-1521-1-ND, TempCo=X7R, Tolerance_%=10%, Value1=Unknown, Value2=25V, ValueDisplayed=0.033uF
C30 C34: "CAP, CERM, 0.018 µF, 50 V,+/- 10%, X7R, 0603", Cap_Case=0603, Manufacturer=MuRata, Supplier Part Number 1=490-1516-1-ND, TempCo=X7R, Tolerance_%=10, Value2=50V, ValueDisplayed=0.018µF
C31: library part CMP-0006585-2, "CAP, CERM, 0.068 uF, 10 V, +/- 10%, X5R, 0402", Cap_Case=0402, Manufacturer=MuRata, Supplier Part Number 1=490-1317-1-ND, TempCo=X5R, Tolerance_%=10%, Value1=Unknown, Value2=10V, ValueDisplayed=0.068uF
C32: library part CMP-0007404-4, "CAP, CERM, 0.1 uF, 25 V, +/- 10%, X7R, 0603", Cap_Case=0603, Manufacturer=MuRata, PartNumber=GRM188R71E104KA01D, Supplier Part Number 1=490-1524-1-ND, TempCo=X7R, Tolerance_%=10%, Value1=Unknown, Value2=25V, ValueDisplayed=0.1uF
C35: library part CMP-0006454-2, "CAP, CERM, 33 pF, 50 V, +/- 5%, C0G/NP0, 0402", Cap_Case=0402, Manufacturer=MuRata, PartNumber=GRM1555C1H330JA01D, Supplier Part Number 1=81-GRM1555C1H330JA1D, TempCo=C0G/NP0, Tolerance_%=5%, Value1=Unknown, Value2=50V, ValueDisplayed=33pF
C36: library part CMP-0007356-5, "CAP, CERM, 2.2 uF, 35 V, +/- 10%, X5R, 0603", Cap_Case=0603, Manufacturer=MuRata, PartNumber=GRM188R6YA225KA12D, Supplier Part Number 1=490-7204-6-ND, TempCo=X5R, Tolerance_%=10%, Value1=Unknown, Value2=35V, ValueDisplayed=2.2uF
C37: "CAP, CERM, 4700 pF, 16 V,+/- 10%, X7R, 0402", Cap_Case=0402, Manufacturer="Wurth Elektronik", Supplier Part Number 1=732-7524-1-ND, TempCo=X7R, Tolerance_%=10, Value2=16V, ValueDisplayed=4700pF
C38: library part CMP-0006486-2, "CAP, CERM, 680 pF, 50 V, +/- 5%, C0G/NP0, 0402", Cap_Case=0402, Manufacturer=MuRata, PartNumber=GRM1555C1H681JA01D, Supplier Part Number 1=490-3240-1-ND, TempCo=C0G/NP0, Tolerance_%=5%, Value1=Unknown, Value2=50V, ValueDisplayed=680pF
C39: library part CMP-0006420-2, "CAP, CERM, 15 pF, 50 V, +/- 5%, C0G/NP0, 0402", Cap_Case=0402, Manufacturer=MuRata, PartNumber=GRM1555C1H150JA01D, Supplier Part Number 1=81-GRM1555C1H150JA1D, TempCo=C0G/NP0, Tolerance_%=5%, Value1=Unknown, Value2=50V, ValueDisplayed=15pF
C40 C41 C42: library part CMP-0006840-4, "CAP, CERM, 100 pF, 50 V, +/- 5%, C0G/NP0, 0603", Cap_Case=0603, Manufacturer=Kemet, PartNumber=C0603C101J5GAC, Supplier Part Number 1=1414602, TempCo=C0G/NP0, Tolerance_%=5%, Value1=Unknown, Value2=50V, ValueDisplayed=100pF
C43 C58: "CAP, CERM, 0.1 µF, 16 V,+/- 5%, X7R, 0603", Cap_Case=0603, Manufacturer=AVX, Supplier Part Number 1=478-3726-1-ND, TempCo=X7R, Tolerance_%=5, Value1="0.039 ohm", Value2=16V, ValueDisplayed=0.1µF
C44 C49 C50: library part CMP-0006339-4, "CAP, CERM, 10 uF, 10 V, +/- 20%, X5R, 0402", Cap_Case=0402, Manufacturer="Samsung Electro-Mechanics", TempCo=X5R, Tolerance_%=20%, Value1=Unknown, Value2=10V, ValueDisplayed=10uF
C45 C46 C47 C48: library part CMP-0006236-2, "CAP, CERM, 0.01 uF, 50 V, +/- 5%, X7R, 0402", Cap_Case=0402, Manufacturer=Kemet, Supplier Part Number 1=399-7758-1-ND, TempCo=X7R, Tolerance_%=5%, Value1=Unknown, Value2=50V, ValueDisplayed=0.01uF
C51: library part CMP-0081100-1, "CAP, CERM, 4.7 µF, 35 V,+/- 20%, X7R, 0805", Cap_Case=0805, Manufacturer=TDK, Supplier Part Number 1=445-7556-1-ND, TempCo=X7R, Tolerance_%=20%, Value2=35V, ValueDisplayed=4.7µF
C52 C53: library part CMP-0009652-3, "CAP, CERM, 220 pF, 50 V, +/- 10%, X7R, AEC-Q200 Grade 1, 0201", Cap_Case=0201_033, Manufacturer=TDK, Supplier Part Number 1=445-12109-1-ND, TempCo=X7R, Tolerance_%=10%, Value1="11.6275 ohm", Value2=50V, ValueDisplayed=220pF
C54 C55: library part CMP-0007844-2, "CAP, CERM, 22 uF, 35 V, +/- 20%, X5R, 0805", Cap_Case=0805, Manufacturer=TDK, Supplier Part Number 1=445-14428-1-ND, TempCo=X5R, Tolerance_%=20%, Value1="0.00205 ohm", Value2=35V, ValueDisplayed=22uF
C56 C57: library part CMP-0006370-2, "CAP, CERM, 0.1 uF, 35 V, +/- 10%, X5R, 0402", Cap_Case=0402, Manufacturer="Taiyo Yuden", Supplier Part Number 1=587-1994-1-ND, TempCo=X5R, Tolerance_%=10%, Value1=Unknown, Value2=35V, ValueDisplayed=0.1uF
C59: library part CMP-0008992-2, "CAP, CERM, 1 uF, 50 V, +/- 10%, X7R, 1206", Cap_Case=1206, Manufacturer=MuRata, Supplier Part Number 1=GRM31MR71H105KA88L-ND, TempCo=X7R, Tolerance_%=10%, Value1=Unknown, Value2=50V, ValueDisplayed=1uF
C60: library part CMP-0007091-5, "CAP, CERM, 2.2 uF, 10 V, +/- 10%, X5R, AEC-Q200 Grade 3, 0603", Cap_Case=0603, Manufacturer=TDK, Supplier Part Number 1=445-12444-1-ND, TempCo=X5R, Tolerance_%=10%, Value1=Unknown, Value2=10V, ValueDisplayed=2.2uF
C62: library part CMP-0007013-5, "CAP, CERM, 0.22 uF, 50 V, +/- 10%, X5R, 0603", Cap_Case=0603, Manufacturer=TDK, Supplier Part Number 1=445-7460-1-ND, TempCo=X5R, Tolerance_%=10%, Value1="0.021699 ohm", Value2=50V, ValueDisplayed=0.22uF
C63: "CAP, CERM, 0.1 µF, 50 V,+/- 20%, X5R, 0402", Cap_Case=0402, Manufacturer=MuRata, Supplier Part Number 1=GRM155R61H104ME14D-ND, TempCo=X5R, Tolerance_%=20, Value2=50V, ValueDisplayed=0.1µF
C64 C65 C66 C67 C68: library part CMP-0008203-2, "CAP, CERM, 22 uF, 16 V, +/- 20%, X5R, 0805", Cap_Case=0805, Manufacturer=MuRata, Supplier Part Number 1=490-9952-1-ND, TempCo=X5R, Tolerance_%=20%, Value1=Unknown, Value2=16V, ValueDisplayed=22uF
CN1: library part CMP-0074939-1, "Terminal Block, 5.08 mm, 4x1, Brass, TH", Color=Blue, Current_A=15A, Manufacturer="On-Shore Technology", Supplier Part Number 1=ED2227-ND, Voltage_V=300V
D1: library part CMP-0002919-2, "LED, White, SMD", Color=White, Manufacturer=OSRAM, Value1=W, Value2=2.8V
J1 J4: "Header, 100mil, 4x1, Gold, TH", Color=Black, Current_A=6.3, Manufacturer=Samtec, Supplier Part Number 1=SAM1029-04-ND, Voltage_V=550
J2: library part CMP-0085712-2, "Receptacle, USB 3.1 Type C, R/A, Gold, SMT", Color=Black, Current_A=1.25A, Manufacturer="JAE Electronics", Voltage_V=20V
L1: library part CMP-0089507-1, "4700nH Shielded Molded Inductor Nonstandard", Digikey Part Number=2184-BMQADY1010404R7MA1CT-ND, Manufacturer="Chilisin Electronics", Operating Temperature Range="-55°C to +125°C", Test Frequency=100kHz, Tolerance_%=20%
L2: library part CMP-0003375-1, "Ferrite Bead, 21 ohm @ 100 MHz, 6 A, 0805", Manufacturer="Taiyo Yuden", Supplier Part Number 1=587-1765-1-ND, Value1="0.004 ohm", Value2=6A, ValueDisplayed="21 ohm"
L3: library part CMP-0056965-1, "Inductor, Shielded, Ferrite, 5.6 uH, 5.5 A, 0.038 ohm, SMD", Manufacturer=Bourns, Supplier Part Number 1=652-SRP6540-5R6M, Value1="0.038 ohm", Value2=5.5A, ValueDisplayed=5.6uH
Logo1: library part CMP-0074838-1, "Texas Instrument Corporate Signature"
Q1 Q2 Q3 Q4: library part CMP-0000589-2, "MOSFET, N-CH, 30 V, 19 A, DNH0008A (VSONP-8)", Alternate Manufacturer=None, Manufacturer="Texas Instruments", Supplier Part Number 1=296-39995-1-ND, Value1=0.006, Value2="13 nC"
R1 R2: library part CMP-0018570-2, "RES, 0.01, 1%, 1 W, 1206", Manufacturer=Vishay-Dale, PartNumber=WSLP1206R0100FEA, Power_W=1W, Supplier Part Number 1=WSLP-.01CT-ND, TempCo="75 ppm/C", Tolerance_%=1%, Value_Code=R010
R3: library part CMP-0018679-3, "RES, 3.9, 5%, 0.25 W, AEC-Q200 Grade 0, 1206", Manufacturer=Vishay-Dale, Power_W=250mW, Supplier Part Number 1=541-3.9ECT-ND, TempCo="200 ppm/C", Tolerance_%=5%, Value2=0.25W, Value_Code=3R90, ValueDisplayed=3.9
R4: library part CMP-0026825-5, "RES, 10 k, 5%, 0.063 W, AEC-Q200 Grade 0, 0402", Manufacturer=Vishay-Dale, Power_W=63mW, Supplier Part Number 1=541-10KJCT-ND, TempCo="200 ppm/C", Tolerance_%=5%, Value2=0.063W, Value_Code=10k0, ValueDisplayed=10k
R5: library part CMP-0022900-4, "RES, 1.00, 1%, 0.1 W, 0603", Manufacturer=Yageo, Power_W=100mW, Supplier Part Number 1=311-1.00HRCT-ND, TempCo="200 ppm/C", Tolerance_%=1%, Value2=0.1W, Value_Code=1R00, ValueDisplayed=1.00
R6 R7: library part CMP-0022478-4, "RES, 4.99, 1%, 0.1 W, AEC-Q200 Grade 0, 0603", Manufacturer=Vishay-Dale, PartNumber=CRCW06034R99FKEA, Power_W=100mW, Supplier Part Number 1=541-4.99HHCT-ND, TempCo="100 ppm/C", Tolerance_%=1%, Value2=0.1W, Value_Code=4R99, ValueDisplayed=4.99
R8 R10: library part CMP-0025703-4, "RES, 10, 5%, 0.1 W, AEC-Q200 Grade 0, 0603", Manufacturer=Vishay-Dale, PartNumber=CRCW060310R0JNEA, Power_W=100mW, Supplier Part Number 1=541-10GCT-ND, TempCo="200 ppm/C", Tolerance_%=5%, Value2=0.1W, Value_Code=10R0, ValueDisplayed=10
R9: library part CMP-0022003-4, "RES, 10.0, 1%, 0.1 W, AEC-Q200 Grade 0, 0603", Manufacturer=Vishay-Dale, PartNumber=CRCW060310R0FKEA, Power_W=100mW, Supplier Part Number 1=541-10.0HCT-ND, TempCo="100 ppm/C", Tolerance_%=1%, Value2=0.1W, Value_Code=10R0
R11: library part CMP-0022362-4, "RES, 383 k, 1%, 0.1 W, AEC-Q200 Grade 0, 0603", Manufacturer=Vishay-Dale, PartNumber=CRCW0603383KFKEA, Power_W=100mW, Supplier Part Number 1=541-383KHCT-ND, TempCo="100 ppm/C", Tolerance_%=1%, Value2=0.1W, Value_Code=383k
R12: library part CMP-0026367-2, "RES, 40.2 k, 1%, 0.063 W, AEC-Q200 Grade 0, 0402", Manufacturer=Vishay-Dale, PartNumber=CRCW040240K2FKED, Power_W=63mW, Supplier Part Number 1=541-40.2KLCT-ND, TempCo="100 ppm/C", Tolerance_%=1%, Value2=0.063W, Value_Code=40k2, ValueDisplayed=40.2k
R13: "RES, 15.0 k, 1%, 0.063 W, 0402", Manufacturer=Vishay-Dale, Power_W=0.063, Supplier Part Number 1=541-15.0KLCT-ND, TempCo="100 ppm/C", Tolerance_%=1, Value1=1%, Value2=0.063W, Value_Code=15k0, ValueDisplayed=15.0k
R14: library part CMP-0022109-5, "RES, 1.00 k, 1%, 0.1 W, AEC-Q200 Grade 0, 0603", Manufacturer=Vishay-Dale, Power_W=100mW, Supplier Part Number 1=541-1.00KHCT-ND, TempCo="100 ppm/C", Tolerance_%=1%, Value2=0.1W, Value_Code=1k00, ValueDisplayed=1.00k
R15 R17: library part CMP-0023343-3, "RES, 0, 1%, 0.1 W, AEC-Q200 Grade 0, 0603", Manufacturer="Stackpole Electronics Inc", Power_W=100mW, Supplier Part Number 1=RMCF0603ZT0R00CT-ND, TempCo=ppm/C, Tolerance_%=1%, Value2=0.1W, Value_Code=0
R16: library part CMP-0022917-4, "RES, 220 k, 1%, 0.1 W, 0603", Manufacturer=Yageo, Power_W=100mW, Supplier Part Number 1=311-220KHRCT-ND, TempCo="100 ppm/C", Tolerance_%=1%, Value2=0.1W, Value_Code=220k
R18: "RES, 1.00 k, 1%, 0.063 W, 0402", Manufacturer=Vishay-Dale, Power_W=0.063, Supplier Part Number 1=541-1.00KLCT-ND, TempCo="100 ppm/C", Tolerance_%=1, Value1=1%, Value2=0.063W, Value_Code=1k00, ValueDisplayed=1.00k
R19 R50: "RES, 10.0 k, 1%, 0.1 W, 0603", Manufacturer=Vishay-Dale, Power_W=0.1, Supplier Part Number 1=541-10.0KHCT-ND, TempCo="100 ppm/C", Tolerance_%=1, Value1=1%, Value2=0.1W, Value_Code=10k0, ValueDisplayed=10.0k
R20: "RES, 191 k, 1%, 0.1 W, 0603", Manufacturer=Vishay-Dale, Power_W=0.1, Supplier Part Number 1=541-191KHCT-ND, TempCo="100 ppm/C", Tolerance_%=1, Value1=1%, Value2=0.1W, Value_Code=191k
R21: library part CMP-0022768-4, "RES, 120 k, 1%, 0.1 W, 0603", Manufacturer=Yageo, Power_W=100mW, Supplier Part Number 1=311-120KHRCT-ND, TempCo="100 ppm/C", Tolerance_%=1%, Value2=0.1W, Value_Code=120k
R22: library part CMP-0022324-4, "RES, 30.1 k, 1%, 0.1 W, AEC-Q200 Grade 0, 0603", Manufacturer=Vishay-Dale, PartNumber=CRCW060330K1FKEA, Power_W=100mW, Supplier Part Number 1=541-30.1KHCT-ND, TempCo="100 ppm/C", Tolerance_%=1%, Value2=0.1W, Value_Code=30k1, ValueDisplayed=30.1k
R23 R25 R27 R32 R33 R39 R41 R46 R48: "RES, 0, 5%, 0.063 W, 0402", Manufacturer="Yageo America", Power_W=0.063, Supplier Part Number 1=311-0.0JRCT-ND, TempCo="200 ppm/C", Tolerance_%=5, Value1=5%, Value2=0.063W, Value_Code=0000, ValueDisplayed=0
R24: library part CMP-0026753-1, "RES, 100 k, 1%, 0.063 W, AEC-Q200 Grade 0, 0402", Manufacturer="Stackpole Electronics Inc", Power_W=63mW, Supplier Part Number 1=RMCF0402FT100KCT-ND, TempCo="100 ppm/C", Tolerance_%=1%, Value2=0.063W, Value_Code=100k
R28 R29 R30 R31: "RES, 2.20 k, 1%, 0.063 W, 0402", Manufacturer=Vishay-Dale, Power_W=0.063, Supplier Part Number 1=541-2.20KLCT-ND, TempCo="100 ppm/C", Tolerance_%=1, Value1=1%, Value2=0.063W, Value_Code=2k20, ValueDisplayed=2.20k
R34 R35 R36 R42 R43 R44 R45: "RES, 10 k, 5%, 0.063 W, 0402", Manufacturer=Vishay-Dale, Power_W=0.063, Supplier Part Number 1=541-10KJCT-ND, TempCo="200 ppm/C", Tolerance_%=5, Value1=5%, Value2=0.063W, Value_Code=10k0, ValueDisplayed=10k
R47: "RES, 30, 5%, 0.063 W, 0402", Manufacturer=Vishay-Dale, Power_W=0.063, Supplier Part Number 1=541-30JCT-ND, TempCo="200 ppm/C", Tolerance_%=5, Value1=5%, Value2=0.063W, Value_Code=30R0, ValueDisplayed=30
R49: "RES, 52.3 k, 1%, 0.1 W, 0603", Manufacturer=Vishay-Dale, Power_W=0.1, Supplier Part Number 1=541-52.3KHCT-ND, TempCo="100 ppm/C", Tolerance_%=1, Value1=1%, Value2=0.1W, Value_Code=52k3, ValueDisplayed=52.3k
S1: library part CMP-0002163-2, "Switch, Slide, SPST, Top Slide, SMT", CurrentRating_mA=100A, Manufacturer="Copal Electronics", Supplier Part Number 1=563-1004-1-ND
U1: library part CMP-0089013-3, "No Description", Manufacturer="Texas Instruments", Operating Temperature Range=to
U2: library part CMP-0090338-2, "USB Type-C and USB PD Controller with Integrated Power Switches Optimized for Power Applications", Manufacturer="Texas Instruments", Max Supply Voltage=22V, Min Supply Voltage=3V, Operating Temperature Range="-40°C to +125°C"
U3: library part CMP-0077834-1, "22-V Precision Surge Protection Clamp, DRV0006A (WSON-6)", Alternate Manufacturer="Texas Instruments"
U4: library part CMP-0005314-2, "256 kb I2C CMOS Serial EEPROM, SOIC-8", Manufacturer="ON Semiconductor", Supplier Part Number 1=CAT24C256WI-G-ND
U5: library part CMP-0035539-1, "Single Output LDO, 150 mA, Fixed 3.3 V Output, 2.7 to 10 V Input, with Low IQ, 5-pin SOT-23 (DBV), -40 to 125 degC, Green (RoHS & no Sb/Br)", Manufacturer="Texas Instruments"
U6: library part CMP-0084209-1, "4.5-V to 24-V Input, 3-A Output Synchronous Step-Down Converter, DDC0006A (SOT-23-THIN-6)", Alternate Manufacturer="Texas Instruments", Alternate PartNumber=TPS56339DDCT

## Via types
v1: diameter 0.4, hole 0.2, Top Layer to Bottom Layer, 1333 vias
v2: diameter 0.406, hole 0.203, Top Layer to Bottom Layer, tented both sides, 81 vias
v3: diameter 0.6, hole 0.3, Top Layer to Bottom Layer, 33 vias
v4: diameter 0.4, hole 0.2, Top Layer to Bottom Layer, tented both sides, 31 vias
v5: diameter 0.5, hole 0.2, Top Layer to Bottom Layer, 26 vias
v6: diameter 0.3, hole 0.2, Top Layer to Bottom Layer, tented both sides, 5 vias
v7: diameter 0.5, hole 0.2, Top Layer to Bottom Layer, tented both sides, 4 vias

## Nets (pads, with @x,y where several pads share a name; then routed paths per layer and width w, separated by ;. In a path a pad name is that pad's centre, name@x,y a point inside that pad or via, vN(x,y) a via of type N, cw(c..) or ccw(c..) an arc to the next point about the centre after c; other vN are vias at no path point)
ADCIN1: R23.2 S1.1 U2.2 | length 11.7
  Top Layer w0.15: U2.2@5.868,26.809 5.868,23.84 8.202,21.506 v4(8.738,21.506)
  Bottom Layer w0.15: v4(8.636,16.662) 8.763,16.789 8.763,21.48 v4(8.738,21.506)
ADCIN2: R23.1 R24.2 U2.3 | length 7.1
  Top Layer w0.15: U2.3@6.268,26.809 6.268,24.041 7.576,22.733 v4(8.738,22.733)
  Bottom Layer w0.15: R23.1@8.81,22.894 8.81,24.222 R24.2@8.812,24.223
BAT: C2.1 C20.1 C32.2 C61.1 C62.1 CN1.4 R2.2 R10.1 R48.2 U6.3 | length 38.6
  Top Layer w0.2: v2(46.778,22.121) 48.914,22.121 49.271,21.765 50.038,21.765
  Top Layer w0.5: C61.1@21.827,3.956 21.827,7.391 U6.3@22.381,7.945 ; R2.2@48.879,21.284 48.975,21.188 C2.1@48.975,17.954
  Bottom Layer w0.15: R10.1@43.848,21.956 43.856,21.948 C32.2@45.112,21.948
  Bottom Layer w0.2: 22.297,3.105 28.356,3.105 29.231,3.98 29.231,7.269 28.188,8.312 v2@27.707,8.312 ; C32.2@45.112,21.948 45.338,22.174 46.725,22.174 v2(46.778,22.121)
  Bottom Layer w0.5: 21.637,1.733 22.424,0.946 v1@33.287,0.946
  other v1: 23.16,0.793 23.689,0.793 24.201,0.793 24.682,0.793 25.195,0.793 26.63,0.793 27.143,0.793 27.656,0.793 28.169,0.793 28.66,0.793 29.173,0.793 29.685,0.793 30.198,0.793 30.878,0.819 31.391,0.819 31.904,0.819 32.417,0.819 32.908,0.819 33.421,0.819 33.933,0.819 34.446,0.819 35.762,0.844 36.275,0.844 36.788,0.844 37.3,0.844 37.791,0.844 38.304,0.844 38.817,0.844 39.33,0.844 40.01,0.87 40.523,0.87 41.036,0.87 41.548,0.87 42.04,0.87 42.552,0.87 43.065,0.87 43.578,0.87 21.94,1.24 21.254,1.265 23.185,1.479 23.714,1.479 24.227,1.479 24.707,1.479 25.22,1.479 25.8,1.471 22.575,1.496 26.63,1.505 27.143,1.505 27.656,1.505 28.169,1.505 28.66,1.505 29.173,1.505 29.685,1.505 30.198,1.505 30.878,1.53 31.391,1.53 31.904,1.53 32.417,1.53 32.908,1.53 33.421,1.53 33.933,1.53 34.446,1.53 35.762,1.555 36.275,1.555 36.788,1.555 37.3,1.555 37.791,1.555 38.304,1.555 38.817,1.555 39.33,1.555 40.01,1.581 40.523,1.581 41.036,1.581 41.548,1.581 42.04,1.581 42.552,1.581 43.065,1.581 43.578,1.581 48.09,1.759 48.619,1.759 49.131,1.759 49.612,1.759 50.125,1.759 21.94,1.768 21.254,1.794 21.94,2.281 21.254,2.307 48.115,2.444 48.644,2.444 49.157,2.444 49.637,2.444 50.15,2.444 21.94,2.762 21.254,2.787 48.09,3.156 48.619,3.156 49.131,3.156 49.612,3.156 50.125,3.156 48.09,3.867 48.619,3.867 49.131,3.867 49.612,3.867 50.125,3.867 48.378,11.159 48.932,11.159 49.471,11.159 49.976,11.159 50.515,11.159 48.404,11.844 48.958,11.844 49.496,11.844 50.002,11.844 50.54,11.844 48.378,12.556 48.932,12.556 49.471,12.556 49.976,12.556 50.515,12.556 48.378,13.267 48.932,13.267 49.471,13.267 49.976,13.267 50.515,13.267 48.417,14.255 48.971,14.255 49.509,14.255 50.015,14.255 50.553,14.255 48.443,14.941 48.997,14.941 49.535,14.941 50.041,14.941 50.579,14.941 48.417,15.652 48.971,15.652 49.509,15.652 50.015,15.652 50.553,15.652 48.417,16.364 48.971,16.364 49.509,16.364 50.015,16.364 50.553,16.364 48.343,17.391 48.897,17.391 49.435,17.391 49.941,17.391 50.479,17.391 48.369,18.077 48.923,18.077 49.461,18.077 49.967,18.077 50.505,18.077 48.343,18.788 48.897,18.788 49.435,18.788 49.941,18.788 50.479,18.788 48.343,19.499 48.897,19.499 49.435,19.499 49.941,19.499 50.479,19.499
  other v2: 27.733,8.321
C_CC1: C53.1 J2.A5 U2.28 | length 15.9
  Top Layer w0.15: v6(3.801,31.259) 3.851,31.309 U2.28@4.568,31.309
  Top Layer w0.2: v2(7.327,40.769) 7.339,40.781 v2(7.339,41.84)
  Bottom Layer w0.15: C53.1@4.588,30.301 4.588,30.946 4.276,31.259 v6(3.801,31.259) 3.791,31.259 3.454,31.596 3.454,38.684 5.715,40.945 7.151,40.945 v2(7.327,40.769)
C_CC2: C52.1 J2.B5 U2.29 | length 17.1
  Top Layer w0.15: v6(3.073,32.233) 3.073,31.527 3.798,30.802 v6(3.801,30.802) 3.956,30.802 4.064,30.909 U2.29@4.568,30.909
  Bottom Layer w0.15: v6@3.073,32.207 v6(3.073,32.233) 3.073,38.837 4.775,40.538 4.775,43.688 5.08,43.993 5.855,43.993 6.089,43.759 v2(6.089,43.44) ; C52.1@3.762,30.311 3.801,30.349 v6(3.801,30.802)
CBL_DIR: U2.36
CSO_N: C31.2 C34.1 R10.2 U1.19 | length 10.3
  Top Layer w0.2: U1.19@34.112,22.39 35.441,22.39 v2(35.71,22.121) v2@35.71,22.096
  Bottom Layer w0.2: v2(35.71,22.121) 37.112,22.121 37.598,21.634 37.598,21.355 38.304,20.649 40.741,20.649 41.302,21.211 C31.2@41.302,21.979 41.325,21.956 R10.2@42.448,21.956
CSO_P: C30.1 C31.1 R8.2 U1.20 | length 10.3
  Top Layer w0.2: U1.20@34.112,22.79 36.176,22.79 36.695,23.309 v2(37.553,23.309)
  Bottom Layer w0.2: C30.1@37.553,23.421 38.873,24.74 40.589,24.74 41.302,24.027 C31.1@41.302,23.179 42.326,23.179 R8.2@42.456,23.309
DTA_RLE: U2.10
FLT_OCP: U2.13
